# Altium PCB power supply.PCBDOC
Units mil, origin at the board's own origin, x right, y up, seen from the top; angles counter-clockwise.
Board outline 2130 x 1570 mil, 2 copper layers (Top Layer, Bottom Layer); 33 components, 17 nets, 87 pads, 16 vias.
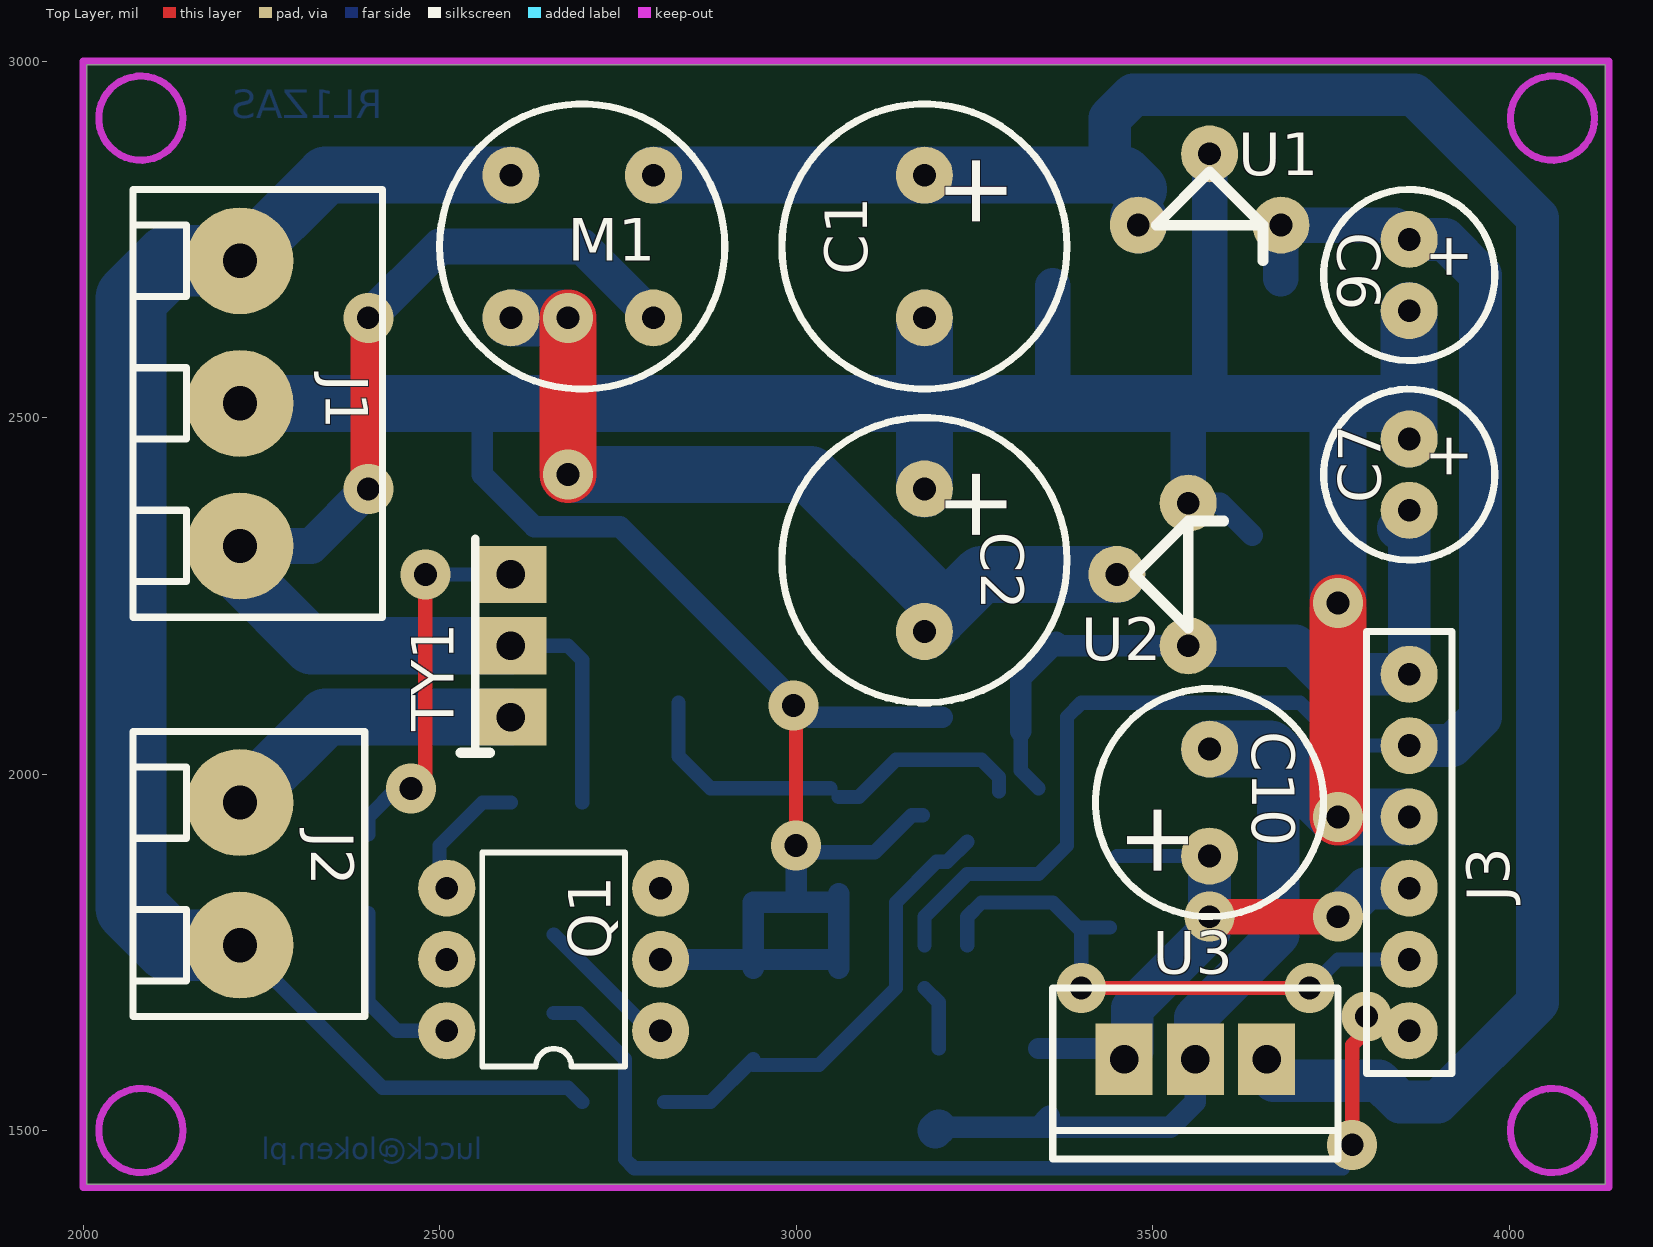
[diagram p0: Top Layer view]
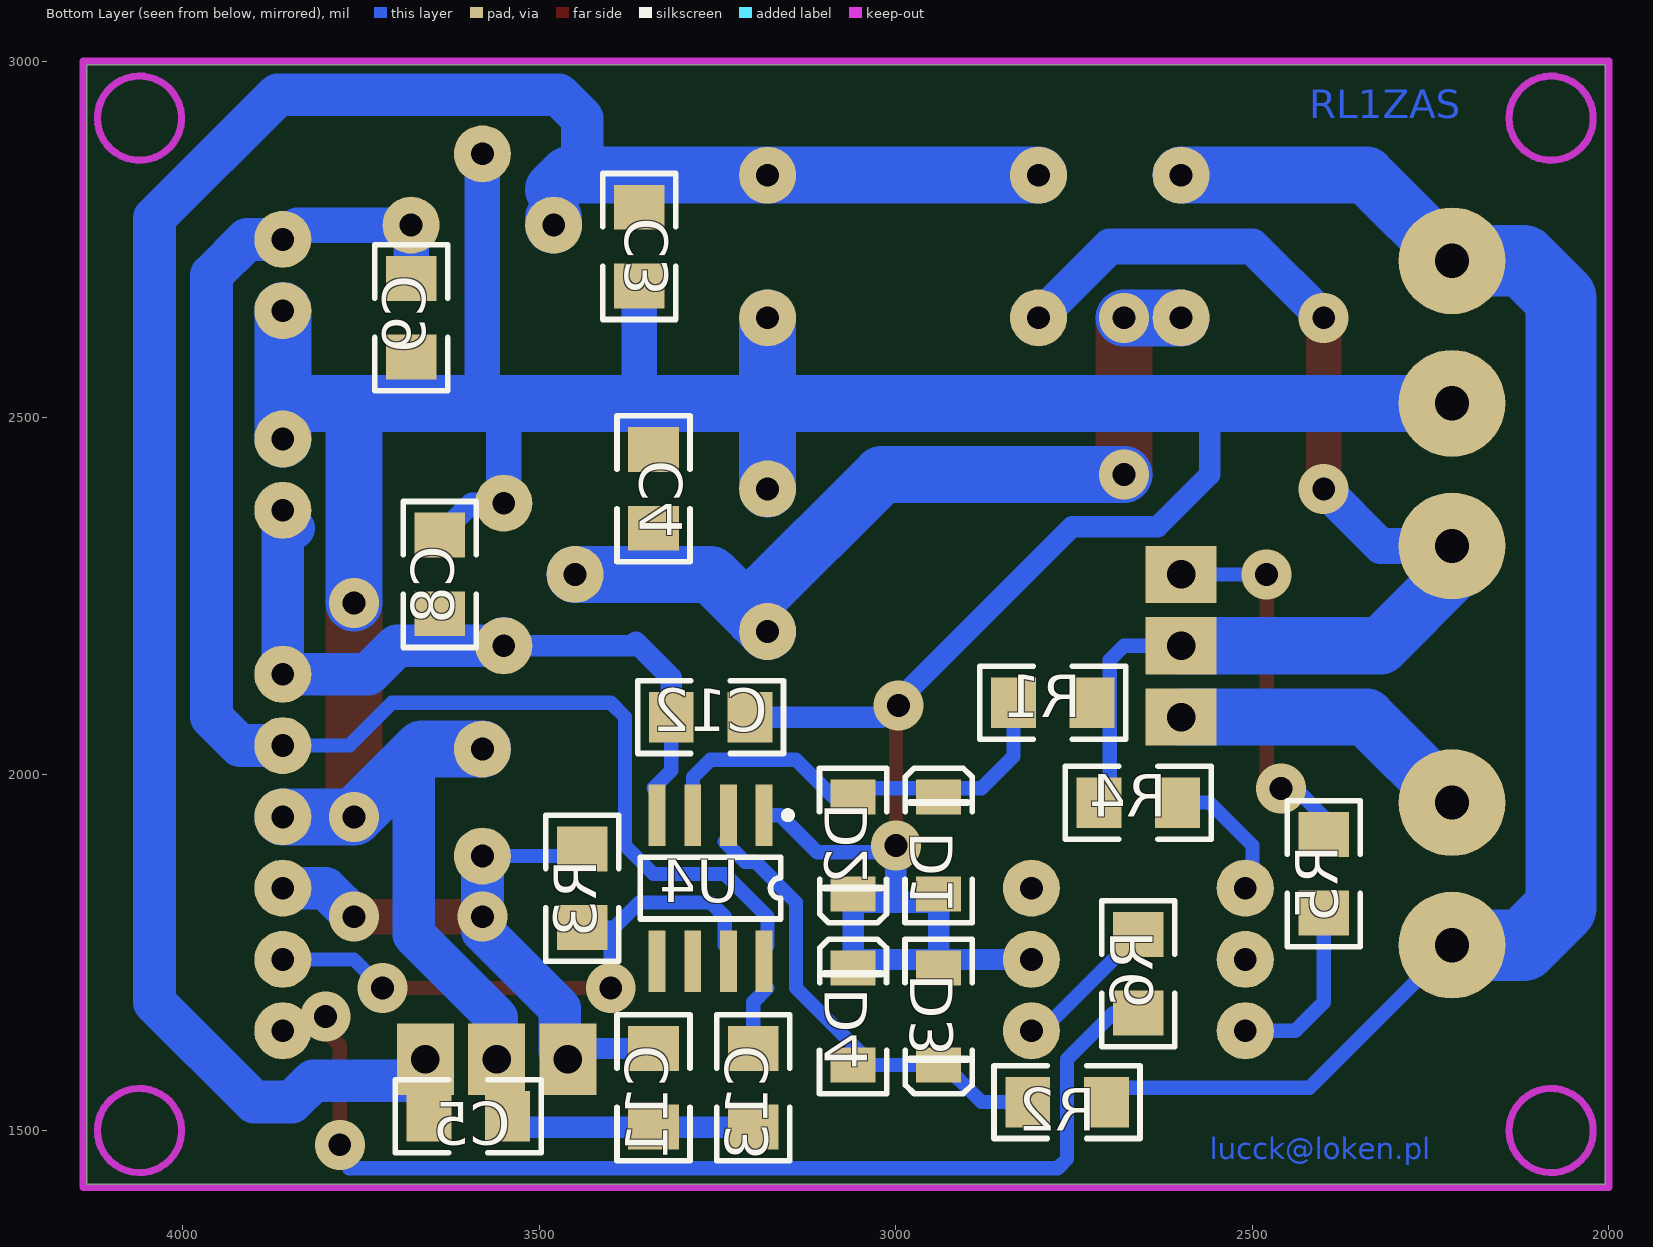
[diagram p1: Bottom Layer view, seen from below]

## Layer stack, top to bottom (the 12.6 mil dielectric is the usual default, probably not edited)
Top Layer: signal copper 1.4
Dielectric: dielectric 12.6, FR-4, Dk 4.8
Bottom Layer: signal copper 1.4

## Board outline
2005,1425 4135,1425 4135,2995 2005,2995

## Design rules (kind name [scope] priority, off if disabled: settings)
Clearance [All] p1: gap=12
ComponentClearance [All] p1: gap=12 collisioncheckmode=2
PolygonConnect [All] p1: connectstyle=Relief reliefconductorwidth=10 reliefentries=4 polygonreliefangle="90 Angle"
RoutingCorners [All] p1: cornerstyle=45-Degree minsetback=25 maxsetback=200
RoutingLayers [All] p1: top layer="Not Used" bottom layer=Any
RoutingVias [All] p1: holewidth=32 width=70 viastyle="Through Hole" minholewidth=32 minwidth=70 maxholewidth=32 maxwidth=100
SolderMaskExpansion [All] p1: expansion=4
TestPointUsage [All] p1: valid=0 allowmultiple=FALSE
Testpoint [All] p1: side=15 testpointundercomponent=TRUE minsize=40 maxsize=100 preferedsize=60 minholesize=0 maxholesize=40 preferedholesize=32 testpointgrid=1 style=1023 order=-539222988
Width [All] p1: maxlimit=200 minlimit=10 preferedwidth=20
15 further rules are at their usual default settings.

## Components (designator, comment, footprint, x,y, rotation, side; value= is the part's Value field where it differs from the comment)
C1 "1000u/25" CE10 3180,2740 r270 top
C2 "1000u/25" CE10 3180,2300 r270 top
C3 "100n" 1206 3360,2740 r270 bottom
C4 "100n" 1206 3340,2400 r270 bottom
C5 "100n" 1206 3600,1520 r180 bottom
C6 "100u/16" CE6 3860,2700 r270 top
C7 "100u/16" CE6 3860,2420 r270 top
C8 "100n" 1206 3640,2280 r270 bottom
C9 "100n" 1206 3680,2640 r270 bottom
C10 "470u/16" CE8 3580,1960 r90 top
C11 "100n" 1206 3340,1560 r270 bottom
C12 "100n" 1206 3260,2080 r180 bottom
C13 "100n" 1206 3200,1560 r270 bottom
D1 "LL4148" MMELF 2940,1900 r90 bottom
D2 "LL4148" MMELF 3060,1900 r270 bottom
D3 "LL4148" MMELF 2940,1660 r270 bottom
D4 "LL4148" MMELF 3060,1660 r90 bottom
J1 "TRAFO" ARK3 2220,2520 r90 top
J2 "GRZALKA" ARK2 2220,1860 r90 top
J3 "CPU" ZL6A 3860,2140 r270 top
M1 "B1000C1500R" MOSTEK1 2700,2740 r180 top
Q1 "MOC3020" U6 2660,1740 r90 top
R1 "10k" 1206 2780,2100 r0 bottom
R2 "10k" 1206 2760,1540 r0 bottom
R3 "1k" 1206 3440,1840 r90 bottom
R4 "220" 1206 2660,1960 r180 bottom
R5 "220" 1206 2400,1860 r270 bottom
R6 "510" 1206 2660,1720 r270 bottom
TY1 "BT136" TYRYSTOR 2600,2180 r90 top
U1 "LM78L09" T 3580,2820 r0 top
U2 "LM79L09" T 3500,2280 r90 top
U3 "LM7805" TO220N 3660,1600 r180 top
U4 "LM311N" SO-G8 3260,1840 r0 bottom

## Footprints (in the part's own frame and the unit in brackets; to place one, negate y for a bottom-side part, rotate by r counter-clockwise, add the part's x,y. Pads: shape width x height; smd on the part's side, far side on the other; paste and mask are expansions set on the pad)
1206 [mm]
  rect 1.6x1.8 smd: 1(-1.4,0) 2(1.4,0)
  silkscreen extent -2.6,-1.3 2.6,1.3
ARK2 [mil]
  round 150 hole 48: 1(-100,0) 2(100,0)
  silkscreen extent -200,-175 200,150
ARK3 [mil]
  round 150 hole 48: 1(-200,0) 2(0,0) 3(200,0)
  silkscreen extent -300,-200 300,150
CE6 [mil]
  round 80 hole 32: 1(-50,0) 2(50,0)
  silkscreen extent -120,-120 120,120
CE8 [mil]
  round 80 hole 32: 1(-75,0) 2(75,0)
  silkscreen extent -160,-160 160,160
CE10 [mil]
  round 80 hole 32: 1(-100,0) 2(100,0)
  silkscreen extent -200,-200 200,200
MMELF [mm]
  rect 1.25x1.6 smd: 1(-1.725,0) 2(1.725,0)
  silkscreen extent -2.75,-1.2 2.76,1.2
MOSTEK1 [mil]
  round 80 hole 32: 1(-100,100) 2(-100,-100) 3(100,-100) 4(100,100)
  silkscreen extent -200,-200 200,200
SO-G8 [mm]
  rect 0.6x2.2 smd: 1(-1.905,-2.6) 2(-0.635,-2.6) 3(0.635,-2.6) 4(1.905,-2.6) 5(1.905,2.6) 6(0.635,2.6) 7(-0.635,2.6) 8(-1.905,2.6)
  silkscreen extent -2.88,-2.72 2.5,1.1
T [mil]
  round 80 hole 32: 1(100,-50) 2(0,50) 3(-100,-50)
  silkscreen extent -75,-100 75,25
TO220N [mil]
  rect 80x100 hole 40: 1(0,0) 2(100,0) 3(200,0)
  silkscreen extent -100,-100 300,140
TYRYSTOR [mil]
  rect 80x100 hole 40: 1(-100,0) 2(0,0) 3(100,0)
  silkscreen extent -150,30 150,70
U6 [mil]
  round 80 hole 32: 1(-100,-150) 2(0,-150) 3(100,-150) 4(100,150) 5(0,150) 6(-100,150)
  silkscreen extent -150,-100 150,100
ZL6A [mil]
  round 80 hole 32: 1(0,0) 2(100,0) 3(200,0) 4(300,0) 5(400,0) 6(500,0)
  silkscreen extent -60,-60 560,60

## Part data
C1 C2 C6 C7 C10: library part EL, "Elektrolit"
C3 C4 C5 C8 C9 C11 C12 C13: library part C, "Kondensator"
D1 D2 D3 D4: library part 1N4148, "Dioda"
J1: library part ARK3, "Z彻cze ARK2"
J2: library part ARK2, "Z彻cze ARK2"
J3: library part CON6, "Z彻cze 6"
M1: library part MOSTEK, "Diode Bridge"
Q1: "Optotriak"
R1 R2 R3 R4 R5 R6: library part R, "Rezystor"
TY1: "Triak"
U1 U2 U3: "stabilizator"
U4: "High-Performance Voltage Comparator"

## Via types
v1: diameter 70, hole 32, Top Layer to Bottom Layer, 16 vias

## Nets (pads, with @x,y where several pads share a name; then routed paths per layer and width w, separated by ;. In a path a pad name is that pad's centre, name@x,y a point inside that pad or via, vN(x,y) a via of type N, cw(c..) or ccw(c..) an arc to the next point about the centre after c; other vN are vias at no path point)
GND: C1.2 C2.1 C3.2 C4.1 C5.2 C6.2 C7.1 C8.1 C9.2 C10.2 C11.2 C12.2 C13.2 D1.1 D2.2 D3.1 D4.2 J1.2 J3.3 Q1.2 U1.2 U2.1 U3.2 U4.1 | length 6599.1
  Top Layer w20: v1(2996.36,2096.36) 3000,2092.73 v1(3000,1900)
  Top Layer w80: v1(3760,1940) v1(3760,2240)
  Bottom Layer w20: v1(3000,1900) 3009.63,1890.37 3110.37,1890.37 3162.36,1942.36 U4.1@3177.64,1942.36
  Bottom Layer w30: 2560,2520 2560,2420 2633,2347 2753,2347 3020,2080 C12.2 ; Q1.2 D4.2@3060,1740 ; D3.1 2940,1820 D2.2@3060,1820 ; v1(2996.36,2096.36) v1@2996.36,2103.64 ; 3000,1820 v1(3000,1900) ; D4.2 D2.2 ; C13.2 3524.88,1504.88 3560,1540 U3.2 ; C11.2 C11.2@3355.12,1520 ; U2.1 3595.12,2380 C8.1
  Bottom Layer w50: C13.2@3195.12,1500 C13.2 ; 3360,2520 C3.2 ; U2.1 3550,2520 ; 3580,2520 U1.2
  Bottom Layer w60: U3.2 3560,1658.18 3676.36,1774.54 3676.36,2023.64 3675.45,2024.55
  Bottom Layer w80: J1.2 3860,2520 ; C2.1 C1.2 ; C10.2 3665,2035 v1(3760,1940) J3.3 ; v1(3760,2240) 3760,2520 ; C7.1 C6.2
GRZ: J3.6 R6.2 | length 1485.9
  Top Layer w20: v1(3780,1480) 3780,1620 v1@3800,1640
  Bottom Layer w20: R6.2 2695.12,1664.88 2760,1600 2760,1460 2773,1447 3767,1447 3767,1467 v1(3780,1480)
  other v1: 3800,1660
M9V: C7.2 C8.2 C12.1 J3.1 U2.3 U4.4 | length 1016.8
  Bottom Layer w20: C12.1@3315.12,2060 3315.12,2004.88 U4.4@3340,1980
  Bottom Layer w30: C12.1@3315.12,2060 3315.12,2135.12 ; 3320,2140 3364.88,2184.88 ; 3360,2180 U2.3
  Bottom Layer w60: U2.3@3540,2180 3700,2180 3740,2140 J3.1 C7.2 ; U2.3 U2.3@3550,2190 ; C7.2@3844.88,2344.88 C7.2@3860,2360
NetC1_1: C1.1 C3.1 C5.1 M1.2 U1.3 U3.1 | length 3004.1
  Bottom Layer w60: 3440,2840 3440,2920 3473,2953 3867,2953 4040,2780 4040,1680 3900,1540 3847.27,1540 3817.24,1570.03 U3.1@3669.97,1570.03
  Bottom Layer w80: M1.2 3460,2840 3480,2820 ; U1.3 U1.3@3480,2780
NetC2_2: C2.2 C4.2 M1.4 U2.2 | length 1217.7
  Top Layer w80: v1(2680,2420) v1(2680,2640)
  Bottom Layer w80: M1.4 v1(2680,2640) ; v1(2680,2420) 3020,2420 3200,2240 C2.2@3200,2220 ; C2.2 3260,2280 U2.2
NetD1_2: D1.2 D2.1 R1.2 U4.3 | length 582.8
  Bottom Layer w20: R1.2 2835.12,2024.88 2880,1980 D2.1@3047.91,1980 ; D2.1 3087.91,1967.91 3140,2020 3260,2020 3284.54,1995.46 U4.3@3284.54,1975.46
NetD3_2: D3.2 D4.1 R2.2 U4.2 | length 649.7
  Bottom Layer w20: R2.2 2880,1540 D3.2@2940,1600 ; D3.2 3032.09,1592.09 3140,1700 3140,1820 3197.05,1877.05 3211.8,1877.05 U4.2@3240,1905.25
NetJ1_1: J1.1 M1.1 R1.1 R4.1 TY1.2 | length 1725.7
  Top Layer w50: v1(2400,2400) v1(2400,2640)
  Bottom Layer w20: TY1.2@2580,2180 2680,2180 2700,2160 R4.1@2700,1960
  Bottom Layer w50: J1.1 2320,2320 v1(2400,2400) ; v1(2400,2640) 2500,2740 2700,2740 M1.1
  Bottom Layer w80: J1.1 2220,2280 2320,2180 TY1.2
NetJ1_3: J1.3 J2.1 M1.3 R2.1 | length 2224.7
  Bottom Layer w20: J2.1 2420,1560 2680,1560 R2.1@2700,1540
  Bottom Layer w60: J1.3 J1.3@2240,2720
  Bottom Layer w80: J1.3 2340,2840 M1.3
  Bottom Layer w100: J2.1 2120,1760 2067,1813 2067,2667 2120,2720 J1.3
NetJ2_2: J2.2 TY1.1 | length 429.7
  Bottom Layer w80: J2.2 2340,2080 TY1.1
NetQ1_1: Q1.1 R6.1 | length 206
  Bottom Layer w20: R6.1 2795.12,1640 Q1.1
NetQ1_4: Q1.4 R4.2 | length 164.9
  Bottom Layer w20: Q1.4@2500,1860 2500,1900 2560,1960 R4.2@2600,1960
NetQ1_6: Q1.6 R5.2 | length 249.7
  Bottom Layer w20: R5.2 2400,1680 2440,1640 2480,1640 Q1.6@2500,1660
NetR5_1: R5.1 TY1.3 | length 529.7
  Top Layer w20: v1(2460,1980) 2480,2000 v1(2480,2280)
  Bottom Layer w20: R5.1 2400,1940 2440,1980 v1(2460,1980) ; v1(2480,2280) TY1.3
P9V: C6.1 C9.1 C13.1 J3.2 U1.1 U4.8 | length 2188.2
  Bottom Layer w20: U4.8@3180,1700 3200,1680 C13.1 ; U4.8@3180,1760 3180,1800 3240,1860 3340,1860 3380,1900 3380,2080 3400,2100 3706.77,2100 3766.77,2040 J3.2
  Bottom Layer w50: C9.1 U1.1 3840,2770 C6.1
  Bottom Layer w60: J3.2 3920,2040 3960,2080 3960,2700 3910,2750 C6.1
VCC: C10.1 C11.1 J3.4 R3.2 U3.3 | length 883.2
  Top Layer w50: v1(3580,1800) v1(3760,1800)
  Bottom Layer w20: R3.2@3450.12,1885 C10.1
  Bottom Layer w30: C11.1 3455.12,1615.12 U3.3@3460,1620
  Bottom Layer w60: U3.3 3471.55,1611.55 3471.55,1671.55 3580,1780 C10.1 ; v1(3760,1800) 3800,1840 J3.4
ZCD: J3.5 R3.1 U4.7 | length 824.3
  Top Layer w20: v1(3400,1700) v1(3720,1700)
  Bottom Layer w20: U4.7@3240,1760 3240,1800 3260,1820 3360,1820 3395.12,1784.88 R3.1 ; v1(3400,1700) 3400,1784.88 ; v1(3720,1700) 3760,1740 J3.5
pads on no net: Q1.3 Q1.5 U4.5 U4.6

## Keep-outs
Keep-Out Layer:
  circle w10: c4060.94,1500 r59.06
  circle w10: c4060.94,2920 r59.06
  circle w10: c2080.94,1500 r59.06
  circle w10: c2080.94,2920 r59.06
  lines w10: 2000,1420 2000,3000 4140,3000 4140,1420 2000,1420

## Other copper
Bottom Layer:
  text "RL1ZAS" at 2420,2920 h40
  text "lucck@loken.pl" at 2560,1460 h30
